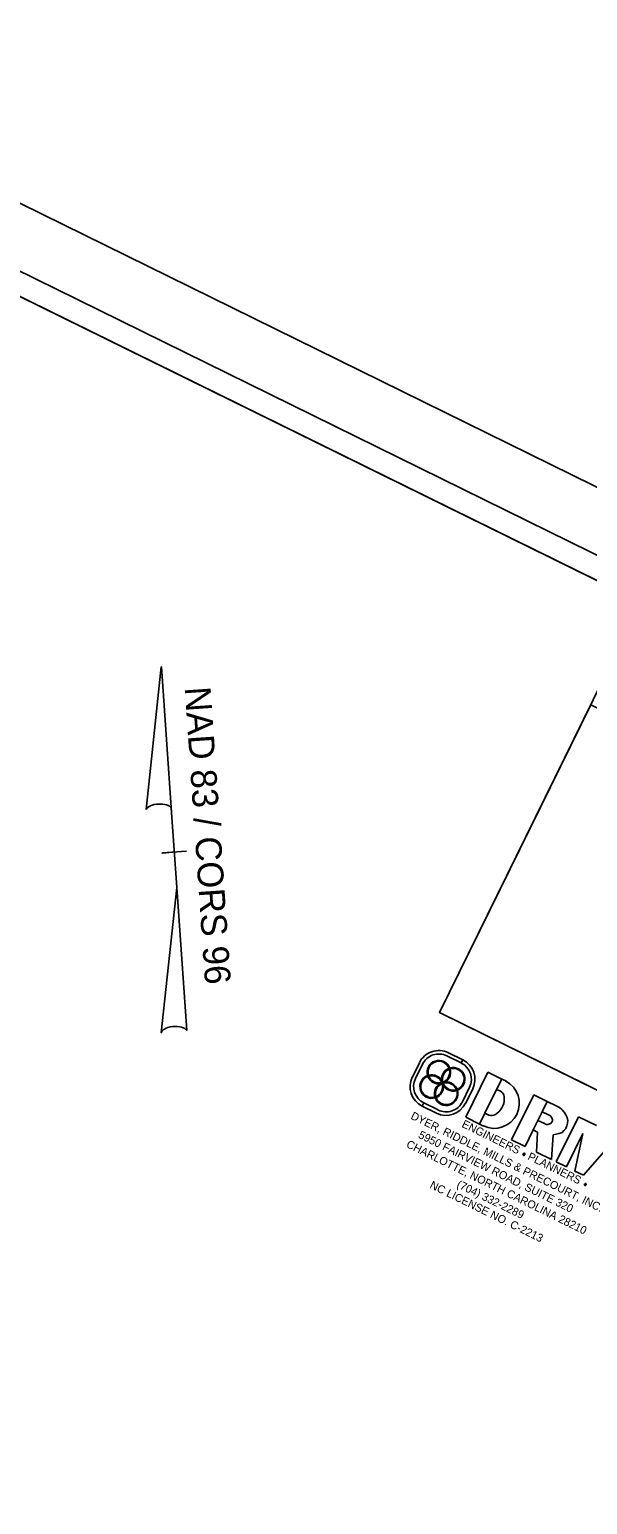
# Model space of a CAD drawing. Extents: x 1428420 to 1430540, y 857897 to 859622.
# Drawn here: x 1430006.3 to 1430189.5, y 858654.2 to 859138.3 of the extents above; entities that cross this region are included whole.
import ezdxf

# ---------------------------------------------------------------- set-up
doc = ezdxf.new("R2010")
doc.units = 0
for name, color, linetype in [('Old_Level_43', 7, 'Continuous'), ('Old_Level_51', 7, 'Continuous'), ('Prop North Arrow NAD83 for Plan Sheets CELL', 7, 'Continuous'), ('Sheet Plan CELL', 7, 'Continuous'), ('Sheet Plot Border Inside CELL', 7, 'Continuous'), ('Sheet Plot Border Outside CELL', 7, 'Continuous')]:
    doc.layers.add(name, color=color, linetype=linetype)

msp = doc.modelspace()

# ---------------------------------------------------------------- linework, layer by layer
at = {"layer": 'Old_Level_51'}
for p, q in [((1430134.36, 858799.22), (1430132.02, 858794.49)), ((1430143.37, 858801.43), (1430148.06, 858799.12)), ((1430148.57, 858800.15), (1430143.87, 858802.46)), ((1430148.06, 858799.12), (1430148.57, 858800.15)), ((1430148.57, 858800.15), (1430148.06, 858799.12)), ((1430133.06, 858793.98), (1430135.39, 858798.71)), ((1430149.55, 858781.31), (1430156.82, 858796.09)), ((1430156.82, 858796.09), (1430149.55, 858781.31)), ((1430161.36, 858793.85), (1430156.82, 858796.09)), ((1430150.78, 858791.14), (1430148.45, 858786.41)), ((1430149.52, 858785.88), (1430151.85, 858790.62)), ((1430155.86, 858782.66), (1430159.69, 858790.46)), ((1430159.69, 858790.46), (1430161.36, 858793.85)), ((1430161.36, 858793.85), (1430159.69, 858790.46)), ((1430159.69, 858790.46), (1430160.95, 858789.84)), ((1430160.95, 858789.84), (1430161.39, 858789.57)), ((1430162.66, 858793.21), (1430161.36, 858793.85)), ((1430161.39, 858789.57), (1430161.76, 858789.16)), ((1430135.77, 858786), (1430135.27, 858784.97)), ((1430135.27, 858784.97), (1430135.77, 858786)), ((1430135.77, 858786), (1430135.27, 858784.97)), ((1430135.27, 858784.97), (1430139.96, 858782.66)), ((1430140.47, 858783.69), (1430135.77, 858786)), ((1430161.74, 858785.08), (1430161.4, 858784.39)), ((1430162.02, 858785.85), (1430161.74, 858785.08)), ((1430161.76, 858789.16), (1430162.02, 858788.64)), ((1430162.02, 858788.64), (1430162.13, 858787.97)), ((1430162.17, 858786.62), (1430162.02, 858785.85)), ((1430162.13, 858787.97), (1430162.17, 858787.29)), ((1430162.17, 858787.29), (1430162.17, 858786.62)), ((1430164.59, 858773.9), (1430171.87, 858788.68)), ((1430171.87, 858788.68), (1430164.59, 858773.9)), ((1430176.3, 858786.51), (1430171.87, 858788.68)), ((1430174.62, 858783.11), (1430176.3, 858786.51)), ((1430176.3, 858786.51), (1430174.62, 858783.11)), ((1430179.28, 858785.04), (1430176.3, 858786.51)), ((1430180.29, 858784.49), (1430179.28, 858785.04)), ((1430149.55, 858781.31), (1430154.09, 858779.07)), ((1430154.09, 858779.07), (1430155.86, 858782.66)), ((1430155.86, 858782.66), (1430154.09, 858779.07)), ((1430157.12, 858782.04), (1430155.86, 858782.66)), ((1430157.62, 858781.89), (1430157.12, 858782.04)), ((1430158.17, 858781.86), (1430157.62, 858781.89)), ((1430158.74, 858781.96), (1430158.17, 858781.86)), ((1430159.29, 858782.21), (1430158.74, 858781.96)), ((1430159.87, 858782.63), (1430159.29, 858782.21)), ((1430160.45, 858783.11), (1430159.87, 858782.63)), ((1430160.97, 858783.71), (1430160.45, 858783.11)), ((1430161.4, 858784.39), (1430160.97, 858783.71)), ((1430171.69, 858777.15), (1430173.23, 858780.28)), ((1430173.23, 858780.28), (1430171.69, 858777.15)), ((1430173.23, 858780.28), (1430174.62, 858783.11)), ((1430175.37, 858779.23), (1430173.23, 858780.28)), ((1430174.62, 858783.11), (1430176.76, 858782.05)), ((1430176.76, 858782.05), (1430177.14, 858781.87)), ((1430177.14, 858781.87), (1430177.43, 858781.68)), ((1430177.43, 858781.68), (1430177.64, 858781.43)), ((1430177.64, 858781.43), (1430177.8, 858781.17)), ((1430177.88, 858779.9), (1430177.75, 858779.62)), ((1430177.8, 858781.17), (1430177.91, 858780.82)), ((1430177.98, 858780.18), (1430177.88, 858779.9)), ((1430177.91, 858780.82), (1430178.01, 858780.54)), ((1430178.01, 858780.54), (1430177.98, 858780.18)), ((1430179.26, 858766.69), (1430186.53, 858781.47)), ((1430186.53, 858781.47), (1430179.26, 858766.69)), ((1430181.13, 858783.8), (1430180.29, 858784.49)), ((1430181.88, 858783), (1430181.13, 858783.8)), ((1430182.38, 858782.09), (1430181.88, 858783)), ((1430182.79, 858781.18), (1430182.38, 858782.09)), ((1430183.08, 858780.23), (1430182.79, 858781.18)), ((1430182.97, 858779.34), (1430183.08, 858780.23)), ((1430192.45, 858778.56), (1430186.53, 858781.47)), ((1430154.09, 858779.07), (1430155.39, 858778.43)), ((1430169.02, 858771.72), (1430171.69, 858777.15)), ((1430171.69, 858777.15), (1430173.14, 858776.44)), ((1430173.14, 858776.44), (1430172.73, 858769.9)), ((1430175.77, 858779.08), (1430175.37, 858779.23)), ((1430176.1, 858778.96), (1430175.77, 858779.08)), ((1430176.44, 858778.98), (1430176.1, 858778.96)), ((1430176.77, 858779.07), (1430176.44, 858778.98)), ((1430177.07, 858779.1), (1430176.77, 858779.07)), ((1430177.37, 858779.24), (1430177.07, 858779.1)), ((1430177.6, 858779.41), (1430177.37, 858779.24)), ((1430177.75, 858779.62), (1430177.6, 858779.41)), ((1430177.65, 858767.48), (1430178.22, 858775.55)), ((1430178.22, 858775.55), (1430179.24, 858775.71)), ((1430179.24, 858775.71), (1430180.21, 858775.95)), ((1430180.21, 858775.95), (1430181.16, 858776.34)), ((1430181.16, 858776.34), (1430181.8, 858776.97)), ((1430181.8, 858776.97), (1430182.35, 858777.6)), ((1430182.35, 858777.6), (1430182.77, 858778.44)), ((1430182.62, 858765.03), (1430187.99, 858775.96)), ((1430182.77, 858778.44), (1430182.97, 858779.34)), ((1430187.99, 858775.96), (1430185.41, 858763.66)), ((1430164.59, 858773.9), (1430169.02, 858771.72)), ((1430188.23, 858762.27), (1430196.48, 858771.79)), ((1430172.73, 858769.9), (1430177.65, 858767.48)), ((1430179.26, 858766.69), (1430182.62, 858765.03)), ((1430185.41, 858763.66), (1430188.23, 858762.27))]:
    msp.add_line(p, q, dxfattribs=at)
for centre, radius, start, end in [((1430140.7, 858796.11), 7.1, 63.6428, 153.8411), ((1430140.7, 858796.11), 5.95, 63.6428, 153.8411), ((1430140.71, 858796.1), 3.86, 20.5636, 196.6241), ((1430140.72, 858796.12), 3.57, 20.4637, 196.7365), ((1430145.45, 858793.77), 7.1, 333.7591, 63.7238), ((1430138.39, 858791.37), 7.13, 153.8411, 243.7577), ((1430138.37, 858791.37), 3.87, 110.548, 287.0077), ((1430138.35, 858791.38), 3.58, 110.5342, 287.0616), ((1430138.37, 858791.37), 3.87, 106.0483, 110.548), ((1430138.37, 858791.37), 3.87, 106.0483, 110.548), ((1430140.71, 858796.1), 3.86, 196.6241, 200.7568), ((1430140.71, 858796.1), 3.86, 196.6235, 213.7966), ((1430138.37, 858791.37), 3.87, 20.5926, 106.0483), ((1430140.72, 858796.12), 3.57, 196.7365, 201.2214), ((1430140.72, 858796.12), 3.57, 196.7355, 285.7543), ((1430138.35, 858791.38), 3.58, 20.5387, 105.6485), ((1430145.44, 858793.76), 3.86, 110.7869, 196.7134), ((1430145.44, 858793.77), 3.57, 111.0814, 196.6342), ((1430140.72, 858796.12), 3.57, 290.5515, 15.8716), ((1430140.71, 858796.1), 3.86, 290.6626, 16.3238), ((1430145.44, 858793.76), 3.86, 106.732, 110.7869), ((1430145.44, 858793.76), 3.86, 106.732, 110.7869), ((1430140.72, 858796.12), 3.57, 15.8716, 20.4637), ((1430140.72, 858796.12), 3.57, 15.8716, 20.4637), ((1430145.44, 858793.77), 3.57, 106.6739, 111.0814), ((1430145.44, 858793.77), 3.57, 106.6739, 111.0814), ((1430145.44, 858793.76), 3.86, 291.044, 106.732), ((1430140.71, 858796.1), 3.86, 16.3238, 20.5636), ((1430140.71, 858796.1), 3.86, 16.3238, 20.5636), ((1430145.44, 858793.77), 3.57, 333.8001, 106.6739), ((1430145.44, 858793.77), 5.95, 333.8048, 63.7944), ((1430138.4, 858791.37), 5.97, 153.8793, 243.7194), ((1430140.71, 858796.1), 3.86, 213.8001, 286.2164), ((1430143.12, 858789.03), 3.87, 110.9378, 196.1662), ((1430143.12, 858789.03), 3.87, 200.5926, 16.8196), ((1430143.14, 858789.03), 3.58, 111.2624, 195.7342), ((1430138.35, 858791.38), 3.58, 291.866, 333.7971), ((1430138.37, 858791.37), 3.87, 291.434, 3.4768), ((1430138.35, 858791.38), 3.58, 333.8001, 16.44), ((1430138.35, 858791.38), 3.58, 16.439, 21.3273), ((1430143.12, 858789.03), 3.87, 107.0077, 111.434), ((1430140.72, 858796.12), 3.57, 286.3527, 291.1016), ((1430145.44, 858793.76), 3.86, 196.0296, 201.1601), ((1430143.12, 858789.03), 3.87, 107.0077, 110.9378), ((1430145.44, 858793.76), 3.86, 196.7134, 201.1601), ((1430140.71, 858796.1), 3.86, 286.7231, 291.1197), ((1430145.44, 858793.76), 3.86, 200.5547, 286.9116), ((1430145.44, 858793.76), 3.86, 200.5547, 213.8367), ((1430143.14, 858789.03), 3.58, 106.5169, 111.2624), ((1430138.37, 858791.37), 3.87, 16.7387, 21.2397), ((1430145.44, 858793.77), 3.57, 195.8918, 201.4269), ((1430140.71, 858796.1), 3.86, 290.6626, 303.9027), ((1430143.14, 858789.03), 3.58, 21.5543, 107.0489), ((1430145.44, 858793.77), 3.57, 200.7695, 286.644), ((1430143.12, 858789.03), 3.87, 21.2034, 93.8001), ((1430143.14, 858789.03), 3.58, 333.8001, 16.8094), ((1430145.44, 858793.77), 3.57, 286.6442, 291.1274), ((1430145.44, 858793.77), 3.57, 286.6442, 291.1273), ((1430143.14, 858789.03), 3.58, 16.8094, 21.5543), ((1430143.14, 858789.03), 3.58, 16.8094, 21.5543), ((1430145.44, 858793.76), 3.86, 286.9117, 291.044), ((1430145.44, 858793.76), 3.86, 286.9117, 291.044), ((1430145.44, 858793.77), 3.57, 291.1274, 333.7971), ((1430143.12, 858789.03), 3.87, 16.8196, 21.2034), ((1430143.12, 858789.03), 3.87, 16.8196, 21.2034), ((1430158.89, 858785.89), 8.23, 244.7757, 62.8246), ((1430158.89, 858785.89), 8.23, 333.8001, 62.8246), ((1430138.35, 858791.38), 3.58, 287.0616, 291.866), ((1430138.35, 858791.38), 3.58, 287.0616, 291.8659), ((1430143.12, 858789.03), 3.87, 196.1662, 200.5926), ((1430143.12, 858789.03), 3.87, 196.1662, 200.5918), ((1430138.37, 858791.37), 3.87, 287.0077, 291.434), ((1430138.37, 858791.37), 3.87, 287.0077, 291.434), ((1430143.14, 858789.03), 3.58, 195.7342, 200.5387), ((1430143.14, 858789.03), 3.58, 195.7342, 200.5386), ((1430143.14, 858789.03), 3.58, 200.5387, 333.7971), ((1430143.1, 858789.05), 7.13, 243.8411, 333.7591), ((1430143.11, 858789.02), 5.95, 243.666, 333.9327), ((1430158.89, 858785.89), 8.23, 244.7757, 333.7987)]:
    msp.add_arc(centre, radius, start, end, dxfattribs=at)
for centre in [(1430168.66, 858769.12), (1430188.78, 858759.22)]:
    msp.add_ellipse(centre, major_axis=(-0.174, -0.353), ratio=0.834135, dxfattribs=at)
at = {"layer": 'Prop North Arrow NAD83 for Plan Sheets CELL'}
for p, q in [((1430044.62, 858882.36), (1430049.61, 858929.16)), ((1430049.66, 858929.16), (1430049.61, 858929.16)), ((1430049.66, 858929.16), (1430049.61, 858929.16)), ((1430049.66, 858929.16), (1430052.95, 858881.48)), ((1430054.66, 858856.74), (1430052.86, 858882.87)), ((1430052.95, 858881.48), (1430052.86, 858882.82)), ((1430049.87, 858868.03), (1430049.82, 858868.03)), ((1430053.41, 858868.28), (1430049.87, 858868.03)), ((1430049.92, 858868.04), (1430057.9, 858868.59)), ((1430054.66, 858856.74), (1430049.58, 858809.02)), ((1430057.95, 858809.8), (1430054.66, 858856.74))]:
    msp.add_line(p, q, dxfattribs=at)
for centre, start_param, end_param in [((1430048.78, 858882.15), 0.216388, 2.908219), ((1430053.82, 858809.15), 0.201328, 3.141593)]:
    msp.add_ellipse(centre, major_axis=(4.22, 0.26), ratio=0.461098, start_param=start_param, end_param=end_param, dxfattribs=at)
at = {"layer": 'Sheet Plan CELL'}
for points in [[(1430386.67, 858862), (1429040.75, 859524.27), (1428581.58, 858591.12), (1429927.48, 857928.86)], [(1428581.58, 858591.12), (1429040.71, 859524.26), (1430207.15, 858950.35), (1430140.91, 858815.69), (1430320.39, 858727.37), (1429927.48, 857928.86)], [(1430190.56, 858916.63), (1430280.34, 858872.46), (1430230.66, 858771.51), (1430140.91, 858815.69)]]:
    msp.add_lwpolyline(points, close=True, dxfattribs=at)
at = {"layer": 'Sheet Plot Border Inside CELL'}
msp.add_lwpolyline([(1428440.55, 858652.15), (1429935.37, 857916.62), (1430401.17, 858863.21), (1428906.33, 859598.76)], close=True, dxfattribs=at)
at = {"layer": 'Sheet Plot Border Outside CELL'}
msp.add_lwpolyline([(1428420.05, 858639.94), (1429930.59, 857896.67), (1430414.03, 858879.17), (1428903.5, 859622.44)], close=True, dxfattribs=at)

# ---------------------------------------------------------------- texts
at = {"layer": 'Old_Level_43'}
for s, p in [('DYER, RIDDLE, MILLS & PRECOURT, INC.', (1430131.24, 858780.9)), ('5950 FAIRVIEW ROAD, SUITE 320', (1430133.74, 858774.66)), ('CHARLOTTE, NORTH CAROLINA 28210', (1430129.78, 858771.61)), ('(704) 332-2289', (1430146.34, 858758.46)), ('NC LICENSE NO. C-2213', (1430137.52, 858758.2))]:
    msp.add_text(s, height=2.6268, rotation=333.8001, dxfattribs=at).set_placement(p)
at = {"layer": 'Old_Level_51'}
for s, p in [('ENGINEERS', (1430148, 858778.23)), ('PLANNERS', (1430169.63, 858767.58))]:
    msp.add_text(s, height=2.627, rotation=333.8001, dxfattribs=at).set_placement(p)
at = {"layer": 'Prop North Arrow NAD83 for Plan Sheets CELL'}
msp.add_text('NAD 83 / CORS 96', height=8.5, rotation=273.9476, dxfattribs=at).set_placement((1430057.26, 858922.34))

doc.saveas('drawing.dxf')
